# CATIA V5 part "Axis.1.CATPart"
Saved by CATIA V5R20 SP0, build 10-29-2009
Part number: Axis.1
Publications: "点.9", "直線.29", "直線.30", "直線.31"
Bounding box of the stored display mesh (mm): x -20 to 20, y -20 to 20, z -20 to 20
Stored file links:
  C:\Work\#01 CATIA Lecture Materials\#299 TOYOTA CATIA V5\TOYOTA_CATIA\LCS\Surface\Surface EX02\Axis.1.CATPart
  C:\Work\#01 CATIA Lecture Materials\#299 TOYOTA CATIA V5\TOYOTA_CATIA\Surface\Surface.3\Axis.2.CATPart
  C:\Work\#01 CATIA Lecture Materials\#299 TOYOTA CATIA V5\TOYOTA_CATIA\Surface\Surface.1\Surface.1_Start.CATProduct
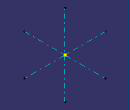
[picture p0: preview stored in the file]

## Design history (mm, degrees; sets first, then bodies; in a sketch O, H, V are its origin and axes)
Set1 "Axis"
  Point1: stored without definition
  Line1 to Line3: stored without definition
Body1 (main body)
